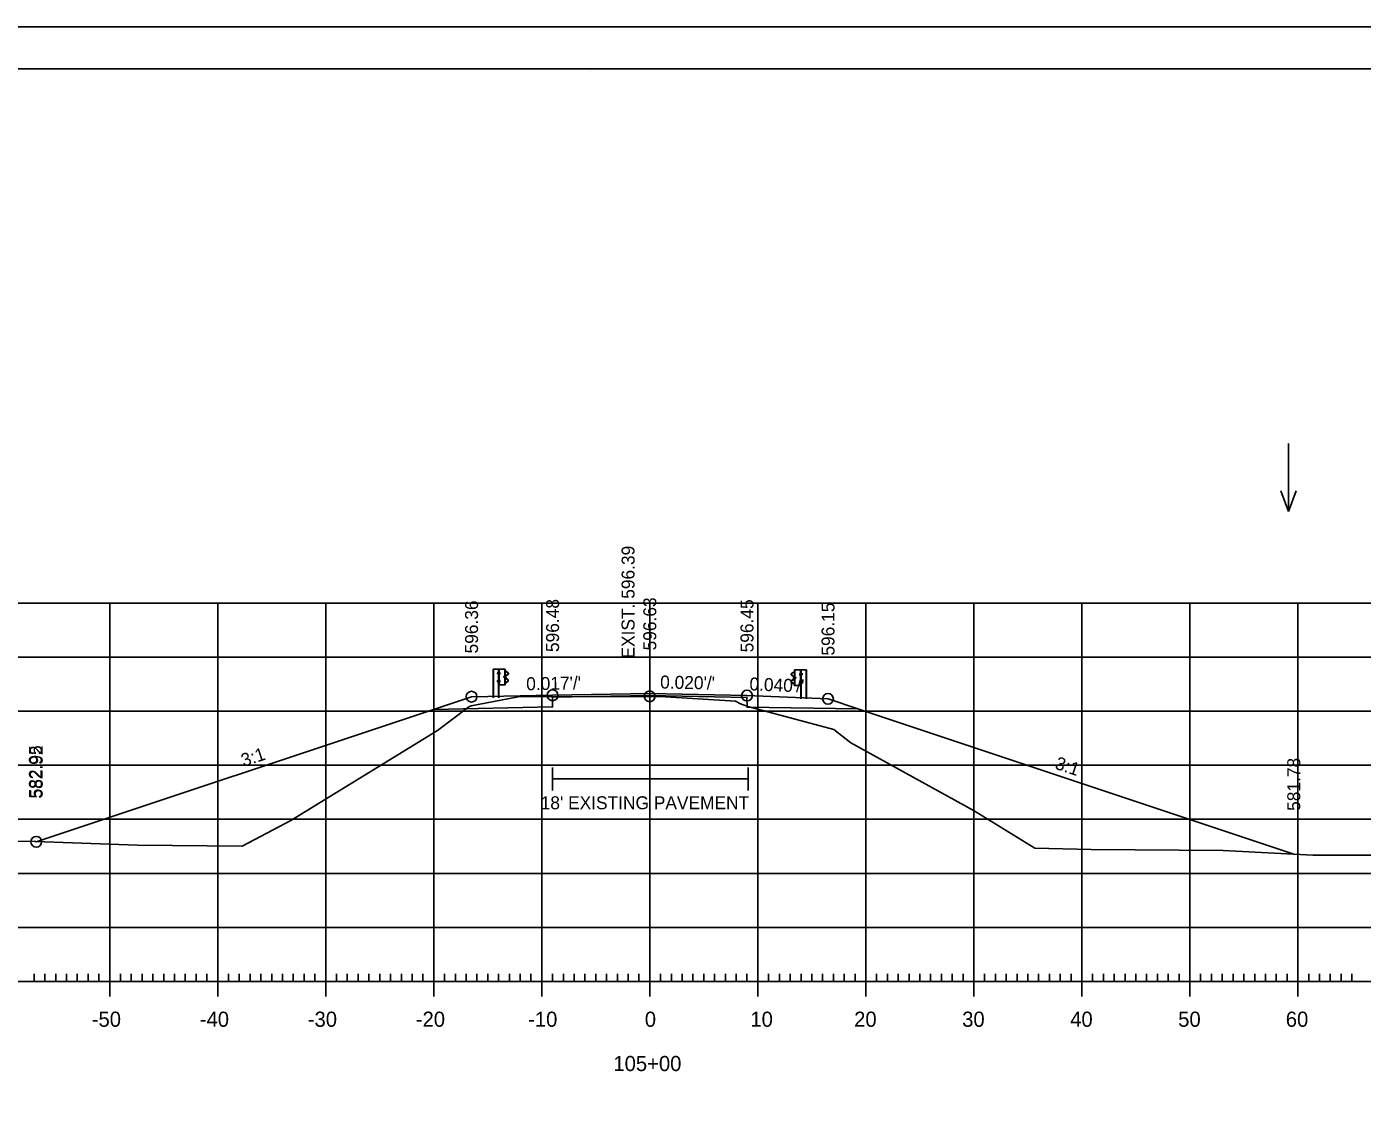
# Model space of a CAD drawing. Extents: x 961436 to 1372525, y 380079 to 2027791.
# Drawn here: x 1370576.1 to 1370699.8, y 380435 to 380535.8 of the extents above; entities that cross this region are included whole.
import ezdxf

# ---------------------------------------------------------------- set-up
doc = ezdxf.new("R2010")
doc.units = 0
for name, color, linetype in [('R_Alt Surface', 7, 'Continuous'), ('R_Axis', 7, 'Continuous'), ('R_Axis Annot', 7, 'Continuous'), ('R_Drive', 7, 'Continuous'), ('R_Exist Surface', 7, 'Continuous'), ('R_Fin Surface', 7, 'Continuous'), ('R_Fin Surface Annot', 7, 'Continuous'), ('R_Grid', 7, 'Continuous'), ('R_No Plot', 7, 'Continuous'), ('R_Proposed Road', 7, 'Continuous'), ('R_Water Annot', 7, 'Continuous'), ('R_Xsect Elev', 7, 'Continuous')]:
    doc.layers.add(name, color=color, linetype=linetype)

msp = doc.modelspace()

# ---------------------------------------------------------------- linework, layer by layer
at = {"layer": 'R_Alt Surface'}
msp.add_lwpolyline([(1370613.78, 380472.57), (1370624.81, 380472.8), (1370624.8, 380472.8), (1370624.81, 380473.71), (1370633.81, 380473.86), (1370642.81, 380473.68), (1370642.82, 380472.77), (1370642.81, 380472.77), (1370653.07, 380472.63)], dxfattribs=at)
at = {"layer": 'R_Axis'}
for p, q in [((1370576.81, 380447.4), (1370576.81, 380448.1)), ((1370577.81, 380447.4), (1370577.81, 380448.1)), ((1370578.81, 380447.4), (1370578.81, 380448.1)), ((1370579.81, 380447.4), (1370579.81, 380448.1)), ((1370580.81, 380447.4), (1370580.81, 380448.1)), ((1370581.81, 380447.4), (1370581.81, 380448.1)), ((1370582.81, 380447.4), (1370582.81, 380448.1)), ((1370583.81, 380446), (1370583.81, 380448.8)), ((1370584.81, 380447.4), (1370584.81, 380448.1)), ((1370585.81, 380447.4), (1370585.81, 380448.1)), ((1370586.81, 380447.4), (1370586.81, 380448.1)), ((1370587.81, 380447.4), (1370587.81, 380448.1)), ((1370588.81, 380447.4), (1370588.81, 380448.1)), ((1370589.81, 380447.4), (1370589.81, 380448.1)), ((1370590.81, 380447.4), (1370590.81, 380448.1)), ((1370591.81, 380447.4), (1370591.81, 380448.1)), ((1370592.81, 380447.4), (1370592.81, 380448.1)), ((1370593.81, 380446), (1370593.81, 380448.8)), ((1370594.81, 380447.4), (1370594.81, 380448.1)), ((1370595.81, 380447.4), (1370595.81, 380448.1)), ((1370596.81, 380447.4), (1370596.81, 380448.1)), ((1370597.81, 380447.4), (1370597.81, 380448.1)), ((1370598.81, 380447.4), (1370598.81, 380448.1)), ((1370599.81, 380447.4), (1370599.81, 380448.1)), ((1370600.81, 380447.4), (1370600.81, 380448.1)), ((1370601.81, 380447.4), (1370601.81, 380448.1)), ((1370602.81, 380447.4), (1370602.81, 380448.1)), ((1370603.81, 380446), (1370603.81, 380448.8)), ((1370604.81, 380447.4), (1370604.81, 380448.1)), ((1370605.81, 380447.4), (1370605.81, 380448.1)), ((1370606.81, 380447.4), (1370606.81, 380448.1)), ((1370607.81, 380447.4), (1370607.81, 380448.1)), ((1370608.81, 380447.4), (1370608.81, 380448.1)), ((1370609.81, 380447.4), (1370609.81, 380448.1)), ((1370610.81, 380447.4), (1370610.81, 380448.1)), ((1370611.81, 380447.4), (1370611.81, 380448.1)), ((1370612.81, 380447.4), (1370612.81, 380448.1)), ((1370613.81, 380446), (1370613.81, 380448.8)), ((1370614.81, 380447.4), (1370614.81, 380448.1)), ((1370615.81, 380447.4), (1370615.81, 380448.1)), ((1370616.81, 380447.4), (1370616.81, 380448.1)), ((1370617.81, 380447.4), (1370617.81, 380448.1)), ((1370618.81, 380447.4), (1370618.81, 380448.1)), ((1370619.81, 380447.4), (1370619.81, 380448.1)), ((1370620.81, 380447.4), (1370620.81, 380448.1)), ((1370621.81, 380447.4), (1370621.81, 380448.1)), ((1370622.81, 380447.4), (1370622.81, 380448.1)), ((1370623.81, 380446), (1370623.81, 380448.8)), ((1370624.81, 380447.4), (1370624.81, 380448.1)), ((1370625.81, 380447.4), (1370625.81, 380448.1)), ((1370626.81, 380447.4), (1370626.81, 380448.1)), ((1370627.81, 380447.4), (1370627.81, 380448.1)), ((1370628.81, 380447.4), (1370628.81, 380448.1)), ((1370629.81, 380447.4), (1370629.81, 380448.1)), ((1370630.81, 380447.4), (1370630.81, 380448.1)), ((1370631.81, 380447.4), (1370631.81, 380448.1)), ((1370632.81, 380447.4), (1370632.81, 380448.1)), ((1370633.81, 380446), (1370633.81, 380448.8)), ((1370634.81, 380447.4), (1370634.81, 380448.1)), ((1370635.81, 380447.4), (1370635.81, 380448.1)), ((1370636.81, 380447.4), (1370636.81, 380448.1)), ((1370637.81, 380447.4), (1370637.81, 380448.1)), ((1370638.81, 380447.4), (1370638.81, 380448.1)), ((1370639.81, 380447.4), (1370639.81, 380448.1)), ((1370640.81, 380447.4), (1370640.81, 380448.1)), ((1370641.81, 380447.4), (1370641.81, 380448.1)), ((1370642.81, 380447.4), (1370642.81, 380448.1)), ((1370643.81, 380446), (1370643.81, 380448.8)), ((1370644.81, 380447.4), (1370644.81, 380448.1)), ((1370645.81, 380447.4), (1370645.81, 380448.1)), ((1370646.81, 380447.4), (1370646.81, 380448.1)), ((1370647.81, 380447.4), (1370647.81, 380448.1)), ((1370648.81, 380447.4), (1370648.81, 380448.1)), ((1370649.81, 380447.4), (1370649.81, 380448.1)), ((1370650.81, 380447.4), (1370650.81, 380448.1)), ((1370651.81, 380447.4), (1370651.81, 380448.1)), ((1370652.81, 380447.4), (1370652.81, 380448.1)), ((1370653.81, 380446), (1370653.81, 380448.8)), ((1370654.81, 380447.4), (1370654.81, 380448.1)), ((1370655.81, 380447.4), (1370655.81, 380448.1)), ((1370656.81, 380447.4), (1370656.81, 380448.1)), ((1370657.81, 380447.4), (1370657.81, 380448.1)), ((1370658.81, 380447.4), (1370658.81, 380448.1)), ((1370659.81, 380447.4), (1370659.81, 380448.1)), ((1370660.81, 380447.4), (1370660.81, 380448.1)), ((1370661.81, 380447.4), (1370661.81, 380448.1)), ((1370662.81, 380447.4), (1370662.81, 380448.1)), ((1370663.81, 380446), (1370663.81, 380448.8)), ((1370664.81, 380447.4), (1370664.81, 380448.1)), ((1370665.81, 380447.4), (1370665.81, 380448.1)), ((1370666.81, 380447.4), (1370666.81, 380448.1)), ((1370667.81, 380447.4), (1370667.81, 380448.1)), ((1370668.81, 380447.4), (1370668.81, 380448.1)), ((1370669.81, 380447.4), (1370669.81, 380448.1)), ((1370670.81, 380447.4), (1370670.81, 380448.1)), ((1370671.81, 380447.4), (1370671.81, 380448.1)), ((1370672.81, 380447.4), (1370672.81, 380448.1)), ((1370673.81, 380446), (1370673.81, 380448.8)), ((1370674.81, 380447.4), (1370674.81, 380448.1)), ((1370675.81, 380447.4), (1370675.81, 380448.1)), ((1370676.81, 380447.4), (1370676.81, 380448.1)), ((1370677.81, 380447.4), (1370677.81, 380448.1)), ((1370678.81, 380447.4), (1370678.81, 380448.1)), ((1370679.81, 380447.4), (1370679.81, 380448.1)), ((1370680.81, 380447.4), (1370680.81, 380448.1)), ((1370681.81, 380447.4), (1370681.81, 380448.1)), ((1370682.81, 380447.4), (1370682.81, 380448.1)), ((1370683.81, 380446), (1370683.81, 380448.8)), ((1370684.81, 380447.4), (1370684.81, 380448.1)), ((1370685.81, 380447.4), (1370685.81, 380448.1)), ((1370686.81, 380447.4), (1370686.81, 380448.1)), ((1370687.81, 380447.4), (1370687.81, 380448.1)), ((1370688.81, 380447.4), (1370688.81, 380448.1)), ((1370689.81, 380447.4), (1370689.81, 380448.1)), ((1370690.81, 380447.4), (1370690.81, 380448.1)), ((1370691.81, 380447.4), (1370691.81, 380448.1)), ((1370692.81, 380447.4), (1370692.81, 380448.1)), ((1370693.81, 380446), (1370693.81, 380448.8)), ((1370694.81, 380447.4), (1370694.81, 380448.1)), ((1370695.81, 380447.4), (1370695.81, 380448.1)), ((1370696.81, 380447.4), (1370696.81, 380448.1)), ((1370697.81, 380447.4), (1370697.81, 380448.1)), ((1370698.81, 380447.4), (1370698.81, 380448.1)), ((1370493.81, 380447.4), (1370773.81, 380447.4))]:
    msp.add_line(p, q, dxfattribs=at)
at = {"layer": 'R_Drive'}
for p, q in [((1370624.8, 380467.21), (1370624.8, 380465.08)), ((1370642.93, 380467.21), (1370642.93, 380465.08)), ((1370624.8, 380466.15), (1370642.93, 380466.15))]:
    msp.add_line(p, q, dxfattribs=at)
at = {"layer": 'R_Exist Surface'}
msp.add_lwpolyline([(1370565.47, 380460.55), (1370576.93, 380460.34), (1370586.39, 380460), (1370596.08, 380459.91), (1370600.59, 380462.28), (1370614.17, 380470.61), (1370617.07, 380472.8), (1370617.28, 380472.91), (1370620.82, 380473.58), (1370621.62, 380473.72), (1370632.41, 380473.78), (1370633.8, 380473.78), (1370634.78, 380473.76), (1370641.76, 380473.32), (1370642.21, 380473.1), (1370642.9, 380472.84), (1370650.86, 380470.72), (1370652.43, 380469.48), (1370663.84, 380463.19), (1370669.47, 380459.73), (1370674.66, 380459.61), (1370686.89, 380459.51), (1370695.19, 380459.09), (1370702.3, 380459.09)], dxfattribs=at)
at = {"layer": 'R_Fin Surface'}
msp.add_lwpolyline([(1370576.93, 380460.34), (1370577.01, 380460.32), (1370613.78, 380472.57), (1370617.31, 380473.75), (1370624.81, 380473.88), (1370633.81, 380474.03), (1370642.81, 380473.85), (1370650.31, 380473.55), (1370653.07, 380472.63), (1370689.45, 380460.51), (1370693.43, 380459.18)], dxfattribs=at)
at = {"layer": 'R_Grid'}
for p, q in [((1370493.81, 380482.4), (1370773.81, 380482.4)), ((1370583.81, 380447.4), (1370583.81, 380482.4)), ((1370593.81, 380447.4), (1370593.81, 380482.4)), ((1370603.81, 380447.4), (1370603.81, 380482.4)), ((1370613.81, 380447.4), (1370613.81, 380482.4)), ((1370623.81, 380447.4), (1370623.81, 380482.4)), ((1370633.81, 380447.4), (1370633.81, 380482.4)), ((1370643.81, 380447.4), (1370643.81, 380482.4)), ((1370653.81, 380447.4), (1370653.81, 380482.4)), ((1370663.81, 380447.4), (1370663.81, 380482.4)), ((1370673.81, 380447.4), (1370673.81, 380482.4)), ((1370683.81, 380447.4), (1370683.81, 380482.4)), ((1370693.81, 380447.4), (1370693.81, 380482.4)), ((1370493.81, 380477.4), (1370773.81, 380477.4)), ((1370493.81, 380472.4), (1370773.81, 380472.4)), ((1370493.81, 380467.4), (1370773.81, 380467.4)), ((1370493.81, 380462.4), (1370773.81, 380462.4)), ((1370493.81, 380457.4), (1370773.81, 380457.4)), ((1370493.81, 380452.4), (1370773.81, 380452.4)), ((1370493.81, 380447.4), (1370773.81, 380447.4))]:
    msp.add_line(p, q, dxfattribs=at)
at = {"layer": 'R_No Plot'}
for p, q in [((1370463.41, 380535.75), (1370796.74, 380535.75)), ((1370475.81, 380531.86), (1370791.99, 380531.86)), ((1370628.33, 380531.6), (1370628.33, 380531.6)), ((1370628.33, 380531.6), (1370628.33, 380531.6))]:
    msp.add_line(p, q, dxfattribs=at)
for points in [[(1370463.4, 380535.75), (1370796.74, 380535.75), (1370796.74, 380322.41), (1370463.4, 380322.41)], [(1370709.73, 380531.86), (1370729.35, 380531.86), (1370729.35, 380521.98), (1370745.46, 380521.98), (1370768.66, 380521.98), (1370768.78, 380493.82), (1370791.99, 380493.82), (1370791.99, 380326.4), (1370475.81, 380326.4), (1370475.81, 380531.86)]]:
    msp.add_lwpolyline(points, close=True, dxfattribs=at)
for centre in [(1370617.31, 380473.75), (1370624.81, 380473.88), (1370633.8, 380473.78), (1370642.81, 380473.85), (1370650.31, 380473.55), (1370577.01, 380460.32)]:
    msp.add_circle(centre, 0.5, dxfattribs=at)
at = {"layer": 'R_Proposed Road'}
for p, q in [((1370619.31, 380476.3), (1370619.31, 380473.63)), ((1370619.34, 380476.3), (1370619.34, 380473.63)), ((1370619.87, 380476.3), (1370619.8, 380476.3)), ((1370619.83, 380473.63), (1370619.83, 380476.3)), ((1370619.87, 380476.3), (1370619.86, 380476.3)), ((1370620.4, 380474.85), (1370620.4, 380476.29)), ((1370620.55, 380476.07), (1370620.43, 380476.14)), ((1370620.54, 380476.06), (1370620.44, 380476.11)), ((1370620.69, 380475.96), (1370620.55, 380476.07)), ((1370647.23, 380474.77), (1370647.23, 380476.21)), ((1370647.75, 380476.22), (1370647.76, 380476.22)), ((1370647.75, 380476.22), (1370647.83, 380476.22)), ((1370647.79, 380473.55), (1370647.79, 380476.22)), ((1370648.28, 380476.22), (1370648.28, 380473.55)), ((1370648.31, 380476.22), (1370648.31, 380473.55)), ((1370619.78, 380475.25), (1370619.73, 380475.25)), ((1370619.73, 380475.13), (1370619.73, 380475.23)), ((1370619.78, 380475.22), (1370619.73, 380475.22)), ((1370619.78, 380475.15), (1370619.73, 380475.15)), ((1370619.78, 380475.12), (1370619.73, 380475.12)), ((1370619.8, 380475.98), (1370619.74, 380475.98)), ((1370619.74, 380475.87), (1370619.74, 380475.96)), ((1370619.8, 380475.95), (1370619.74, 380475.95)), ((1370619.8, 380475.88), (1370619.74, 380475.88)), ((1370619.8, 380475.85), (1370619.74, 380475.85)), ((1370619.78, 380475.15), (1370619.74, 380475.15)), ((1370619.8, 380475.88), (1370619.75, 380475.88)), ((1370619.78, 380475.12), (1370619.78, 380475.25)), ((1370619.8, 380475.85), (1370619.8, 380475.98)), ((1370619.87, 380474.85), (1370619.83, 380474.85)), ((1370619.93, 380475.91), (1370619.87, 380475.91)), ((1370619.93, 380475.18), (1370619.87, 380475.18)), ((1370619.88, 380475.98), (1370619.93, 380475.98)), ((1370619.88, 380475.84), (1370619.93, 380475.84)), ((1370619.93, 380475.25), (1370619.88, 380475.25)), ((1370619.93, 380475.12), (1370619.88, 380475.12)), ((1370619.93, 380475.98), (1370619.93, 380475.84)), ((1370619.93, 380475.12), (1370619.93, 380475.25)), ((1370620.39, 380475.64), (1370620.33, 380475.64)), ((1370620.33, 380475.52), (1370620.33, 380475.62)), ((1370620.39, 380475.61), (1370620.33, 380475.61)), ((1370620.39, 380475.54), (1370620.33, 380475.54)), ((1370620.39, 380475.51), (1370620.33, 380475.51)), ((1370620.39, 380475.54), (1370620.34, 380475.54)), ((1370620.39, 380475.51), (1370620.39, 380475.64)), ((1370620.43, 380475.02), (1370620.54, 380475.08)), ((1370620.44, 380475.51), (1370620.44, 380475.65)), ((1370620.44, 380475), (1370620.56, 380475.06)), ((1370620.47, 380475.51), (1370620.47, 380475.65)), ((1370620.49, 380475.72), (1370620.67, 380475.83)), ((1370620.65, 380475.33), (1370620.49, 380475.43)), ((1370620.5, 380475.7), (1370620.69, 380475.81)), ((1370620.66, 380475.35), (1370620.5, 380475.45)), ((1370620.68, 380475.95), (1370620.54, 380476.06)), ((1370620.54, 380475.08), (1370620.68, 380475.2)), ((1370620.56, 380475.06), (1370620.69, 380475.18)), ((1370646.93, 380475.88), (1370647.07, 380475.99)), ((1370647.07, 380474.98), (1370646.93, 380475.1)), ((1370647.12, 380475.62), (1370646.94, 380475.73)), ((1370646.95, 380475.87), (1370647.09, 380475.98)), ((1370647.13, 380475.64), (1370646.95, 380475.75)), ((1370647.08, 380475), (1370646.95, 380475.12)), ((1370646.96, 380475.27), (1370647.13, 380475.37)), ((1370646.97, 380475.25), (1370647.14, 380475.35)), ((1370647.07, 380475.99), (1370647.19, 380476.06)), ((1370647.19, 380474.92), (1370647.07, 380474.98)), ((1370647.2, 380474.94), (1370647.08, 380475)), ((1370647.09, 380475.98), (1370647.18, 380476.03)), ((1370647.16, 380475.43), (1370647.16, 380475.57)), ((1370647.18, 380475.43), (1370647.18, 380475.57)), ((1370647.24, 380475.43), (1370647.24, 380475.56)), ((1370647.24, 380475.56), (1370647.29, 380475.56)), ((1370647.24, 380475.53), (1370647.29, 380475.53)), ((1370647.24, 380475.46), (1370647.28, 380475.46)), ((1370647.24, 380475.46), (1370647.29, 380475.46)), ((1370647.24, 380475.43), (1370647.29, 380475.43)), ((1370647.3, 380475.44), (1370647.3, 380475.54)), ((1370647.75, 380475.9), (1370647.7, 380475.9)), ((1370647.7, 380475.9), (1370647.7, 380475.76)), ((1370647.7, 380475.83), (1370647.76, 380475.83)), ((1370647.75, 380475.76), (1370647.7, 380475.76)), ((1370647.7, 380475.04), (1370647.7, 380475.17)), ((1370647.7, 380475.17), (1370647.75, 380475.17)), ((1370647.7, 380475.1), (1370647.76, 380475.1)), ((1370647.7, 380475.04), (1370647.75, 380475.04)), ((1370647.83, 380475.77), (1370647.83, 380475.9)), ((1370647.83, 380475.9), (1370647.88, 380475.9)), ((1370647.83, 380475.87), (1370647.88, 380475.87)), ((1370647.83, 380475.8), (1370647.87, 380475.8)), ((1370647.83, 380475.8), (1370647.88, 380475.8)), ((1370647.83, 380475.77), (1370647.88, 380475.77)), ((1370647.84, 380475.04), (1370647.84, 380475.17)), ((1370647.84, 380475.17), (1370647.89, 380475.17)), ((1370647.84, 380475.14), (1370647.89, 380475.14)), ((1370647.84, 380475.07), (1370647.89, 380475.07)), ((1370647.84, 380475.07), (1370647.89, 380475.07)), ((1370647.84, 380475.04), (1370647.89, 380475.04)), ((1370647.89, 380475.79), (1370647.89, 380475.88)), ((1370647.9, 380475.05), (1370647.9, 380475.15)), ((1370647.76, 380474.77), (1370647.79, 380474.77))]:
    msp.add_line(p, q, dxfattribs=at)
for points in [[(1370619.31, 380476.3), (1370619.8, 380476.3), (1370619.79, 380473.63)], [(1370648.31, 380476.22), (1370647.83, 380476.22), (1370647.83, 380473.55)]]:
    msp.add_lwpolyline(points, dxfattribs=at)
for points in [[(1370620.43, 380476.3), (1370620.43, 380474.85), (1370619.87, 380474.85), (1370619.87, 380476.3)], [(1370647.2, 380476.22), (1370647.2, 380474.77), (1370647.76, 380474.77), (1370647.75, 380476.22)], [(1370619.72, 380475.22), (1370619.72, 380475.15), (1370619.7, 380475.15), (1370619.7, 380475.22)], [(1370619.73, 380475.95), (1370619.73, 380475.88), (1370619.71, 380475.88), (1370619.71, 380475.95)], [(1370619.78, 380475.27), (1370619.78, 380475.09), (1370619.79, 380475.09), (1370619.79, 380475.27)], [(1370619.79, 380476), (1370619.79, 380475.82), (1370619.8, 380475.82), (1370619.8, 380476)], [(1370619.93, 380475.98), (1370619.93, 380475.84), (1370619.87, 380475.84), (1370619.87, 380475.98)], [(1370619.93, 380475.25), (1370619.93, 380475.12), (1370619.87, 380475.12), (1370619.87, 380475.25)], [(1370620.33, 380475.61), (1370620.33, 380475.54), (1370620.3, 380475.54), (1370620.3, 380475.61)], [(1370620.38, 380475.66), (1370620.38, 380475.48), (1370620.4, 380475.48), (1370620.4, 380475.66)], [(1370647.24, 380475.58), (1370647.24, 380475.4), (1370647.23, 380475.4), (1370647.23, 380475.58)], [(1370647.3, 380475.53), (1370647.3, 380475.46), (1370647.33, 380475.46), (1370647.33, 380475.53)], [(1370647.7, 380475.9), (1370647.7, 380475.76), (1370647.75, 380475.76), (1370647.75, 380475.9)], [(1370647.7, 380475.17), (1370647.7, 380475.04), (1370647.75, 380475.04), (1370647.75, 380475.17)], [(1370647.83, 380475.92), (1370647.83, 380475.74), (1370647.82, 380475.74), (1370647.82, 380475.92)], [(1370647.84, 380475.19), (1370647.84, 380475.01), (1370647.83, 380475.01), (1370647.83, 380475.19)], [(1370647.89, 380475.87), (1370647.89, 380475.8), (1370647.92, 380475.8), (1370647.92, 380475.87)], [(1370647.9, 380475.14), (1370647.9, 380475.07), (1370647.93, 380475.07), (1370647.93, 380475.14)]]:
    msp.add_lwpolyline(points, close=True, dxfattribs=at)
for centre, radius, start, end in [((1370619.75, 380475.23), 0.0234, 134.5745, 222.2244), ((1370619.82, 380475.18), 0.0979, 159.7423, 200.2577), ((1370619.75, 380475.13), 0.0265, 140.9334, 216.6234), ((1370619.76, 380475.96), 0.0234, 134.5745, 222.2244), ((1370619.84, 380475.91), 0.0979, 159.7423, 200.2577), ((1370619.76, 380475.86), 0.0265, 140.9334, 216.6234), ((1370620.35, 380475.62), 0.0234, 134.5745, 222.2244), ((1370620.43, 380475.57), 0.0979, 159.7423, 200.2577), ((1370620.35, 380475.52), 0.0265, 140.9334, 216.6234), ((1370620.53, 380475.64), 0.0918, 118.106, 175.0444), ((1370620.51, 380475.5), 0.0747, 171.7804, 246.8536), ((1370620.46, 380475.57), 0.0481, 282.9554, 86.0697), ((1370620.53, 380475.64), 0.066, 118.106, 175.0444), ((1370620.51, 380475.5), 0.049, 171.7804, 246.8536), ((1370620.6, 380475.25), 0.0907, 325.2184, 59.12), ((1370620.6, 380475.25), 0.116, 325.2184, 59.12), ((1370620.64, 380475.89), 0.0658, 299.2499, 57.9783), ((1370620.64, 380475.89), 0.0909, 299.2499, 57.9783), ((1370646.98, 380475.81), 0.0909, 122.0217, 240.7501), ((1370647.02, 380475.17), 0.116, 120.88, 214.7816), ((1370646.98, 380475.81), 0.0658, 122.0217, 240.7501), ((1370647.02, 380475.17), 0.0907, 120.88, 214.7816), ((1370647.09, 380475.56), 0.066, 4.9556, 61.894), ((1370647.16, 380475.49), 0.0481, 93.9303, 257.0446), ((1370647.09, 380475.56), 0.0918, 4.9556, 61.894), ((1370647.11, 380475.42), 0.049, 293.1464, 8.2196), ((1370647.11, 380475.42), 0.0747, 293.1464, 8.2196), ((1370647.27, 380475.54), 0.0234, 317.7756, 45.4255), ((1370647.2, 380475.49), 0.0979, 339.7423, 20.2577), ((1370647.27, 380475.44), 0.0265, 323.3766, 39.0666), ((1370647.86, 380475.88), 0.0234, 317.7756, 45.4255), ((1370647.79, 380475.83), 0.0979, 339.7423, 20.2577), ((1370647.86, 380475.78), 0.0265, 323.3766, 39.0666), ((1370647.88, 380475.15), 0.0234, 317.7756, 45.4255), ((1370647.8, 380475.1), 0.0979, 339.7423, 20.2577), ((1370647.87, 380475.05), 0.0265, 323.3766, 39.0666)]:
    msp.add_arc(centre, radius, start, end, dxfattribs=at)
at = {"layer": 'R_Water Annot'}
for p, q in [((1370692.94, 380497.17), (1370692.94, 380490.89)), ((1370692.94, 380490.89), (1370692.24, 380492.81)), ((1370692.94, 380490.89), (1370693.64, 380492.81))]:
    msp.add_line(p, q, dxfattribs=at)

# ---------------------------------------------------------------- texts
at = {"layer": 'R_Axis Annot'}
for s, p in [('-50', (1370582.15, 380443.2)), ('-40', (1370592.15, 380443.2)), ('-30', (1370602.15, 380443.2)), ('-20', (1370612.15, 380443.2)), ('-10', (1370622.55, 380443.2)), ('0', (1370633.35, 380443.2)), ('10', (1370643.12, 380443.2)), ('20', (1370652.73, 380443.2)), ('30', (1370662.73, 380443.2)), ('40', (1370672.73, 380443.2)), ('50', (1370682.73, 380443.2)), ('60', (1370692.69, 380443.2)), ('105+00', (1370630.44, 380439.1))]:
    msp.add_text(s, height=1.4, dxfattribs=at).set_placement(p)
at = {"layer": 'R_Fin Surface Annot'}
for s, rotation, p in [('596.36', 90, (1370617.91, 380477.75)), ('596.48', 90, (1370625.41, 380477.88)), ('596.63', 90, (1370634.41, 380478.03)), ('596.45', 90, (1370643.41, 380477.85)), ('596.15', 90, (1370650.91, 380477.55)), ("0.017'/'", 0.9661, (1370622.38, 380474.34)), ("0.020'/'", 358.8542, (1370634.76, 380474.51)), ("0.040'/'", 357.7094, (1370643.02, 380474.34)), ('582.95', 90, (1370577.53, 380464.34)), ('582.92', 90, (1370577.61, 380464.32)), ('3:1', 18.4349, (1370596.21, 380467.25)), ('3:1', 341.5651, (1370671.24, 380467.1)), ('581.78', 90, (1370694.03, 380463.18))]:
    msp.add_text(s, height=1.2, rotation=rotation, dxfattribs=at).set_placement(p)
msp.add_text("18' EXISTING PAVEMENT", height=1.2, dxfattribs=at).set_placement((1370623.71, 380463.33))
at = {"layer": 'R_Xsect Elev'}
msp.add_text('EXIST. 596.39', height=1.2, rotation=90, dxfattribs=at).set_placement((1370632.4, 380477.28))

doc.saveas('drawing.dxf')
